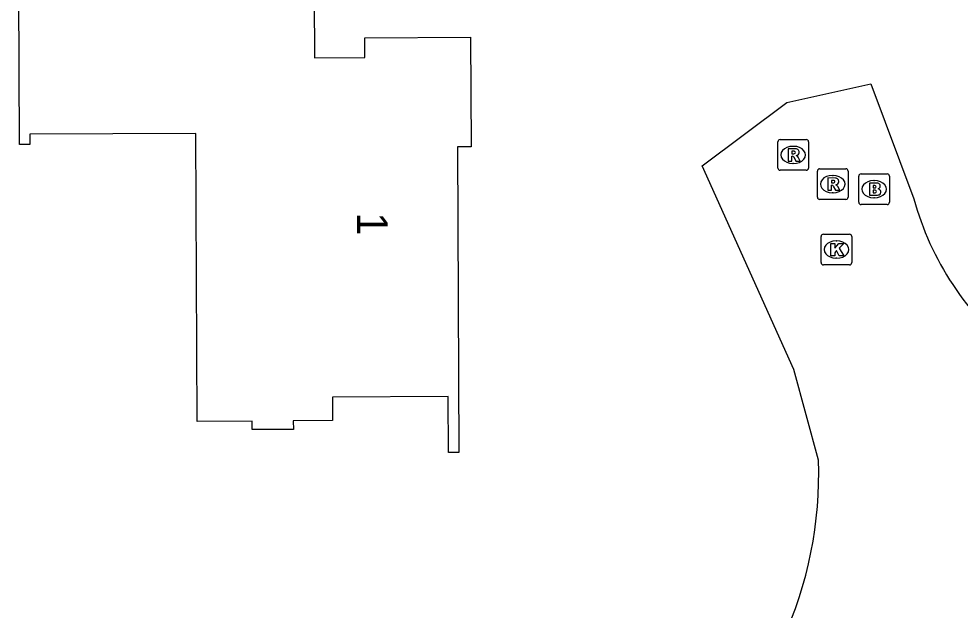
# Model space of a CAD drawing. Extents: x 163268 to 164360, y 381529 to 382285.
# Drawn here: x 163955.38 to 163986.03, y 381951.19 to 381970.46 of the extents above; entities that cross this region are included whole.
import ezdxf

# ---------------------------------------------------------------- set-up
doc = ezdxf.new("R2010")
doc.units = 0
for name, color, linetype in [('IMGEO_Brandkraan', 7, 'Continuous'), ('IMGEO_Kolk', 7, 'Continuous'), ('IMGEO_Pand', 7, 'Continuous'), ('IMGEO_Pand_nummerreeks', 7, 'Continuous'), ('IMGEO_Rioolput', 7, 'Continuous'), ('IMGEO_Voetpad_open', 7, 'Continuous')]:
    doc.layers.add(name, color=color, linetype=linetype)

msp = doc.modelspace()

# ---------------------------------------------------------------- linework, layer by layer
at = {"layer": 'IMGEO_Brandkraan'}
for p, q in [((163982.802, 381965.405), (163983.654, 381965.405)), ((163982.727, 381964.479), (163982.727, 381965.331)), ((163983.215, 381965.185), (163983.24, 381965.185)), ((163983.728, 381965.331), (163983.728, 381964.479)), ((163983.238, 381964.625), (163983.213, 381964.625)), ((163983.654, 381964.405), (163982.802, 381964.405))]:
    msp.add_line(p, q, dxfattribs=at)
for points in [[(163982.802, 381965.405), (163983.654, 381965.405)], [(163982.727, 381964.479), (163982.727, 381965.331)], [(163983.075, 381965.105), (163983.075, 381964.705), (163983.288, 381964.705)], [(163983.306, 381965.105), (163983.075, 381965.105)], [(163983.728, 381965.331), (163983.728, 381964.479)], [(163983.254, 381965.024), (163983.2, 381965.024), (163983.2, 381964.948)], [(163983.2, 381964.948), (163983.253, 381964.948)], [(163983.262, 381964.872), (163983.2, 381964.872), (163983.2, 381964.791)], [(163983.2, 381964.791), (163983.262, 381964.791)], [(163983.654, 381964.405), (163982.802, 381964.405)]]:
    msp.add_lwpolyline(points, dxfattribs=at)
for centre, radius, start, end in [((163982.804, 381965.329), 0.0765, 91.552, 178.448), ((163982.804, 381965.329), 0.0765, 91.552, 178.448), ((163983.652, 381965.329), 0.0765, 1.552, 88.448), ((163983.652, 381965.329), 0.0765, 1.552, 88.448), ((163983.31, 381964.96), 0.145, 59.4692, 91.5367), ((163983.335, 381965.007), 0.0922, 285.5137, 58.1501), ((163983.255, 381964.986), 0.0379, 267.8285, 90.9355), ((163983.263, 381964.831), 0.0404, 269.8759, 90.5077), ((163983.34, 381964.815), 0.105, 301.3115, 78.989), ((163982.804, 381964.481), 0.0765, 181.552, 268.448), ((163982.804, 381964.481), 0.0765, 181.552, 268.448), ((163983.294, 381964.956), 0.251, 268.6676, 293.5347), ((163983.652, 381964.481), 0.0765, 271.552, 358.448), ((163983.652, 381964.481), 0.0765, 271.552, 358.448)]:
    msp.add_arc(centre, radius, start, end, dxfattribs=at)
for centre, major_axis, ratio, start_param, end_param in [((163983.214, 381964.905), (-0.387, 0.002), 0.722429, 4.712389, 7.853982), ((163983.239, 381964.905), (-0.39, 0.002), 0.717154, 1.570796, 4.712389)]:
    msp.add_ellipse(centre, major_axis=major_axis, ratio=ratio, start_param=start_param, end_param=end_param, dxfattribs=at)
at = {"layer": 'IMGEO_Kolk'}
for p, q in [((163981.499, 381962.512), (163981.499, 381963.364)), ((163981.574, 381963.438), (163982.426, 381963.438)), ((163981.987, 381963.218), (163982.012, 381963.218)), ((163982.5, 381963.364), (163982.5, 381962.512)), ((163982.01, 381962.658), (163981.985, 381962.658)), ((163982.426, 381962.438), (163981.574, 381962.438))]:
    msp.add_line(p, q, dxfattribs=at)
for points in [[(163981.499, 381962.512), (163981.499, 381963.364)], [(163981.574, 381963.438), (163982.426, 381963.438)], [(163982.5, 381963.364), (163982.5, 381962.512)], [(163981.82, 381963.138), (163981.943, 381963.138), (163981.943, 381962.987), (163982.073, 381963.138), (163982.237, 381963.138), (163982.091, 381962.987), (163982.244, 381962.738), (163982.092, 381962.738), (163982.007, 381962.902), (163981.943, 381962.835), (163981.943, 381962.738), (163981.82, 381962.738), (163981.82, 381963.138)], [(163982.426, 381962.438), (163981.574, 381962.438)]]:
    msp.add_lwpolyline(points, dxfattribs=at)
for centre, start, end in [((163981.576, 381963.362), 91.552, 178.448), ((163981.576, 381963.362), 91.552, 178.448), ((163982.424, 381963.362), 1.552, 88.448), ((163982.424, 381963.362), 1.552, 88.448), ((163981.576, 381962.514), 181.552, 268.448), ((163981.576, 381962.514), 181.552, 268.448), ((163982.424, 381962.514), 271.552, 358.448), ((163982.424, 381962.514), 271.552, 358.448)]:
    msp.add_arc(centre, 0.0765, start, end, dxfattribs=at)
for centre, major_axis, ratio, start_param, end_param in [((163981.986, 381962.938), (-0.387, 0.002), 0.722429, 4.712389, 7.853982), ((163982.011, 381962.938), (-0.39, 0.002), 0.717154, 1.570796, 4.712389)]:
    msp.add_ellipse(centre, major_axis=major_axis, ratio=ratio, start_param=start_param, end_param=end_param, dxfattribs=at)
at = {"layer": 'IMGEO_Pand'}
msp.add_lwpolyline([(163964.971, 381976.95), (163965.008, 381969.189), (163966.652, 381969.196), (163966.649, 381969.838), (163970.088, 381969.854), (163970.105, 381966.282), (163969.663, 381966.28), (163969.71, 381956.322), (163969.371, 381956.321), (163969.362, 381958.15), (163965.59, 381958.132), (163965.593, 381957.369), (163964.32, 381957.363), (163964.321, 381957.08), (163962.982, 381957.074), (163962.981, 381957.348), (163961.193, 381957.339), (163961.149, 381966.722), (163955.741, 381966.696), (163955.742, 381966.357), (163955.408, 381966.356), (163955.384, 381971.299)], dxfattribs=at)
at = {"layer": 'IMGEO_Rioolput'}
for p, q in [((163980.092, 381965.595), (163980.092, 381966.447)), ((163980.167, 381966.521), (163981.019, 381966.521)), ((163980.58, 381966.301), (163980.605, 381966.301)), ((163981.093, 381966.447), (163981.093, 381965.595)), ((163980.603, 381965.741), (163980.578, 381965.741)), ((163981.019, 381965.521), (163980.167, 381965.521)), ((163981.379, 381964.645), (163981.379, 381965.497)), ((163981.454, 381965.571), (163982.306, 381965.571)), ((163981.867, 381965.351), (163981.892, 381965.351)), ((163982.38, 381965.497), (163982.38, 381964.645)), ((163981.89, 381964.791), (163981.865, 381964.791)), ((163982.306, 381964.571), (163981.454, 381964.571))]:
    msp.add_line(p, q, dxfattribs=at)
for points in [[(163980.092, 381965.595), (163980.092, 381966.447)], [(163980.167, 381966.521), (163981.019, 381966.521)], [(163981.093, 381966.447), (163981.093, 381965.595)], [(163980.681, 381966.219), (163980.429, 381966.221), (163980.429, 381965.821)], [(163980.429, 381965.821), (163980.553, 381965.821), (163980.553, 381965.983), (163980.564, 381965.983)], [(163980.607, 381966.14), (163980.553, 381966.14), (163980.553, 381966.059)], [(163980.553, 381966.059), (163980.605, 381966.059)], [(163980.611, 381965.954), (163980.682, 381965.821), (163980.822, 381965.821), (163980.757, 381965.947)], [(163981.019, 381965.521), (163980.167, 381965.521)], [(163981.379, 381964.645), (163981.379, 381965.497)], [(163981.454, 381965.571), (163982.306, 381965.571)], [(163982.38, 381965.497), (163982.38, 381964.645)], [(163981.968, 381965.269), (163981.716, 381965.271), (163981.716, 381964.871)], [(163981.894, 381965.19), (163981.84, 381965.19), (163981.84, 381965.109)], [(163981.84, 381965.109), (163981.892, 381965.109)], [(163981.716, 381964.871), (163981.84, 381964.871), (163981.84, 381965.033), (163981.851, 381965.033)], [(163981.898, 381965.004), (163981.969, 381964.871), (163982.109, 381964.871), (163982.044, 381964.997)], [(163982.306, 381964.571), (163981.454, 381964.571)]]:
    msp.add_lwpolyline(points, dxfattribs=at)
for centre, radius, start, end in [((163980.169, 381966.445), 0.0765, 91.552, 178.448), ((163980.169, 381966.445), 0.0765, 91.552, 178.448), ((163981.017, 381966.445), 0.0765, 1.552, 88.448), ((163981.017, 381966.445), 0.0765, 1.552, 88.448), ((163980.563, 381965.93), 0.0533, 26.0293, 88.6989), ((163980.589, 381966.248), 0.19, 274.7715, 282.9687), ((163980.613, 381966.044), 0.0964, 77.0061, 93.1865), ((163980.627, 381966.101), 0.0378, 276.6634, 79.6772), ((163980.68, 381966.109), 0.109, 350.3612, 89.416), ((163980.678, 381966.109), 0.112, 277.5842, 350.9817), ((163980.662, 381965.894), 0.108, 29.5134, 73.7905), ((163980.169, 381965.597), 0.0765, 181.552, 268.448), ((163980.169, 381965.597), 0.0765, 181.552, 268.448), ((163981.017, 381965.597), 0.0765, 271.552, 358.448), ((163981.017, 381965.597), 0.0765, 271.552, 358.448), ((163981.456, 381965.495), 0.0765, 91.552, 178.448), ((163981.456, 381965.495), 0.0765, 91.552, 178.448), ((163982.304, 381965.495), 0.0765, 1.552, 88.448), ((163982.304, 381965.495), 0.0765, 1.552, 88.448), ((163981.876, 381965.298), 0.19, 274.7715, 282.9687), ((163981.9, 381965.094), 0.0964, 77.0061, 93.1865), ((163981.914, 381965.151), 0.0378, 276.6634, 79.6772), ((163981.967, 381965.159), 0.109, 350.3612, 89.416), ((163981.965, 381965.159), 0.112, 277.5842, 350.9817), ((163981.949, 381964.944), 0.108, 29.5134, 73.7905), ((163981.85, 381964.98), 0.0533, 26.0293, 88.6989), ((163981.456, 381964.647), 0.0765, 181.552, 268.448), ((163981.456, 381964.647), 0.0765, 181.552, 268.448), ((163982.304, 381964.647), 0.0765, 271.552, 358.448), ((163982.304, 381964.647), 0.0765, 271.552, 358.448)]:
    msp.add_arc(centre, radius, start, end, dxfattribs=at)
for centre, major_axis, ratio, start_param, end_param in [((163980.579, 381966.021), (-0.387, 0.002), 0.722429, 4.712389, 7.853982), ((163980.604, 381966.021), (-0.39, 0.002), 0.717154, 1.570796, 4.712389), ((163981.866, 381965.071), (-0.387, 0.002), 0.722429, 4.712389, 7.853982), ((163981.891, 381965.071), (-0.39, 0.002), 0.717154, 1.570796, 4.712389)]:
    msp.add_ellipse(centre, major_axis=major_axis, ratio=ratio, start_param=start_param, end_param=end_param, dxfattribs=at)
at = {"layer": 'IMGEO_Voetpad_open'}
msp.add_lwpolyline([(163981.414, 381956.081), (163980.616, 381959.035), (163977.632, 381965.668), (163980.388, 381967.726), (163983.118, 381968.332), (163984.519, 381964.593)], dxfattribs=at)
for centre, radius, start, end in [((163993.963, 381967.188), 9.794, 195.3619, 231.4685), ((163968.539, 381955.596), 12.884, 335.1798, 2.1592)]:
    msp.add_arc(centre, radius, start, end, dxfattribs=at)

# ---------------------------------------------------------------- texts
at = {"layer": 'IMGEO_Pand_nummerreeks'}
msp.add_text('1', height=1, rotation=270.2691, dxfattribs=at).set_placement((163966.393, 381964.147))

doc.saveas('drawing.dxf')
